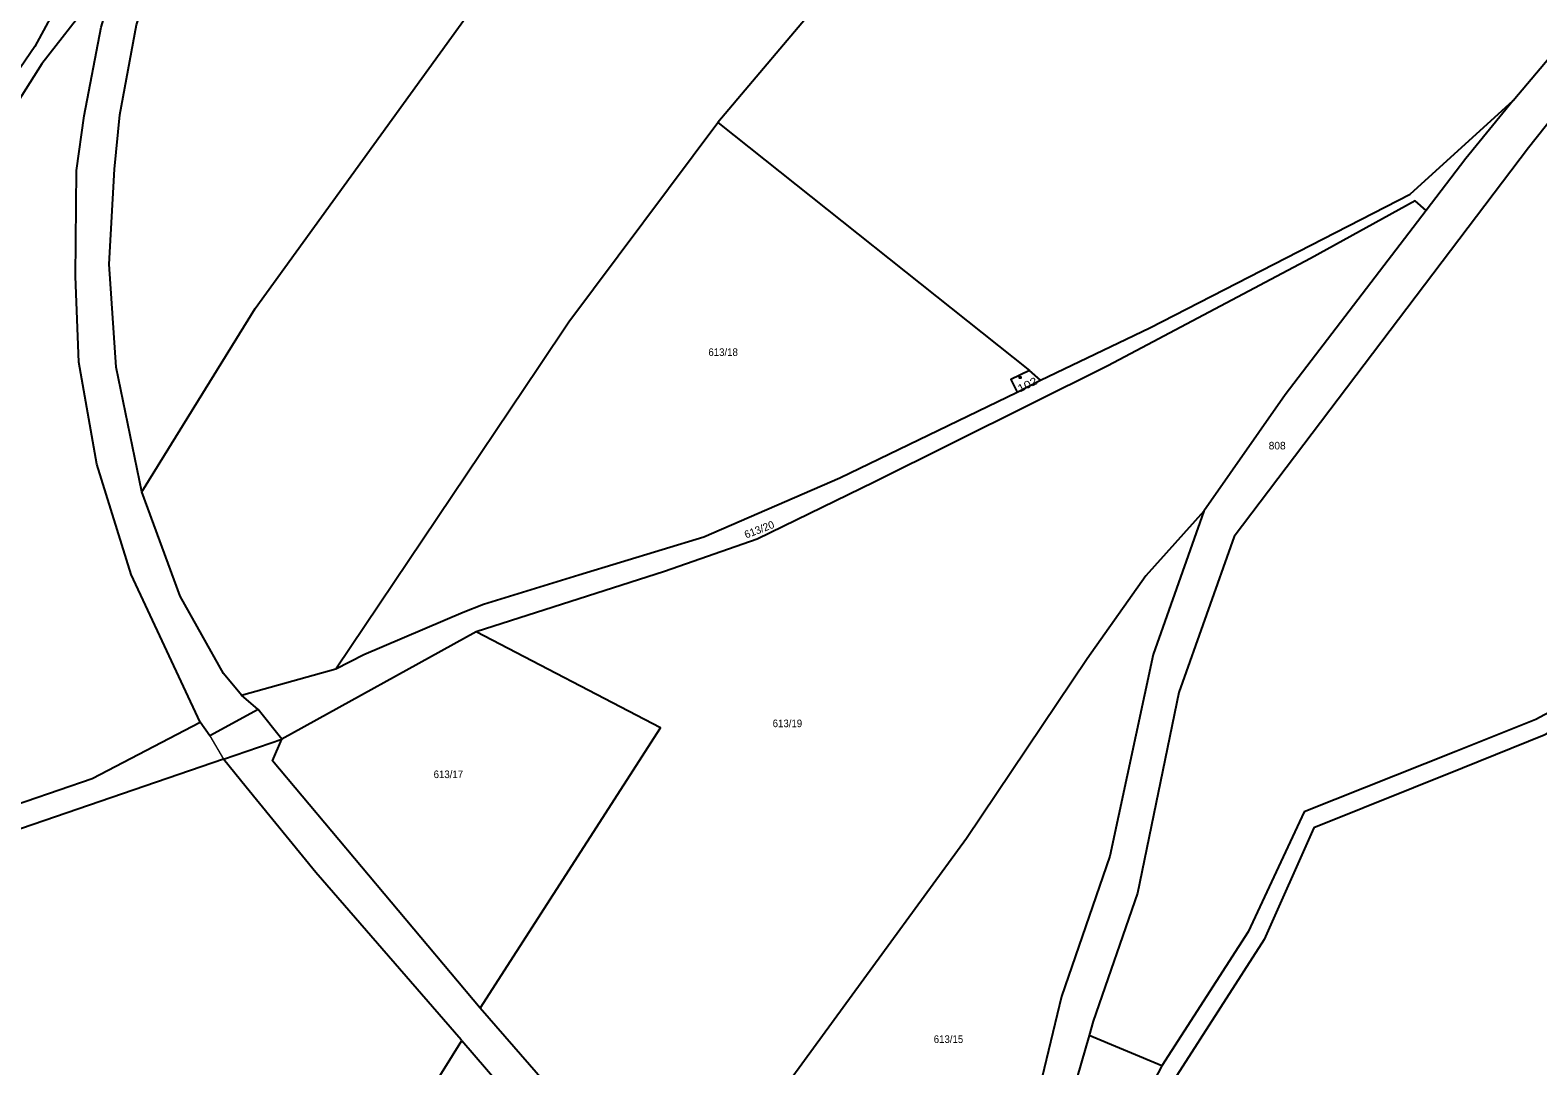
# Model space of a CAD drawing. Extents: x -687135 to -684370, y -1007309 to -1005782.
# Drawn here: x -684920.8 to -684583, y -1006550 to -1006317.9 of the extents above; entities that cross this region are included whole.
import ezdxf

# ---------------------------------------------------------------- set-up
doc = ezdxf.new("R2010")
doc.units = 0
doc.header["$LTSCALE"] = 0.68
for name, color, linetype, lineweight in [('1', 7, 'Continuous', 25), ('4', 7, 'Continuous', 13), ('5', 7, 'Continuous', 25)]:
    doc.layers.add(name, color=color, linetype=linetype, lineweight=lineweight)
doc.layers.add('2', color=7, linetype='Continuous')

msp = doc.modelspace()

# ---------------------------------------------------------------- linework, layer by layer
at = {"layer": '1'}
for p, q in [((-684820.88, -1006452.76), (-684864.38, -1006476.83)), ((-684873.47, -1006466.92), (-684852.35, -1006461.07)), ((-684869.72, -1006470.15), (-684873.47, -1006466.92)), ((-684667.28, -1006550.01), (-684683.56, -1006543.2))]:
    msp.add_line(p, q, dxfattribs=at)
for points in [[(-684895.75, -1006421.4), (-684901.52, -1006393.47), (-684903.13, -1006370.41), (-684901.9, -1006349.06), (-684900.72, -1006336.88), (-684896.95, -1006316.71), (-684891.31, -1006300.08), (-684874.68, -1006263.75), (-684861.12, -1006245.83), (-684849.13, -1006233.21), (-684838.04, -1006222.1), (-684820.16, -1006207.64), (-684803.79, -1006195.44), (-684787.9, -1006184.05), (-684728.55, -1006143.87), (-684695.61, -1006119.67)], [(-684895.75, -1006421.4), (-684870.4, -1006380.29), (-684822.32, -1006313.86), (-684813.73, -1006302.51), (-684789.44, -1006271.88), (-684758.27, -1006233.58), (-684701.91, -1006153.06), (-684685.37, -1006125.92), (-684682.73, -1006121.59)], [(-684594.2, -1006128.33), (-684596.65, -1006135.63), (-684614.36, -1006156.02), (-684631.3, -1006178.22), (-684688.55, -1006244.87), (-684727.25, -1006290.89), (-684742.63, -1006309.98), (-684766.71, -1006338.61), (-684696.92, -1006394.18)], [(-684465.61, -1006201.09), (-684474.26, -1006204.25), (-684488.16, -1006218.72), (-684538.26, -1006285.17), (-684585.17, -1006344.33), (-684651.09, -1006431.43), (-684663.47, -1006466.37), (-684672.76, -1006511.35), (-684682.63, -1006539.99), (-684683.56, -1006543.2)], [(-684856.23, -1006219.78), (-684868.36, -1006236.18), (-684877.16, -1006249.29), (-684887.91, -1006266.51), (-684898.63, -1006286.6), (-684913.88, -1006310.63), (-684919.75, -1006321.58), (-684931.87, -1006339.19), (-684939.11, -1006350.34), (-684952.01, -1006369.9), (-684965.12, -1006392.2), (-684970.59, -1006402.96), (-684973.76, -1006410.29), (-684980.32, -1006434.42)], [(-684588.56, -1006333.7), (-684566.02, -1006306.89), (-684551.05, -1006289.44)], [(-684900.57, -1006302.99), (-684907.23, -1006311.42), (-684918.18, -1006325.47), (-684932.07, -1006347.35), (-684944, -1006366.68), (-684955.53, -1006384.87), (-684969.03, -1006410.25), (-684975.28, -1006437.24), (-684977.83, -1006474.8), (-684979.92, -1006493.97)], [(-684882.68, -1006473.01), (-684898.16, -1006439.92), (-684905.85, -1006415.18), (-684909.93, -1006392.37), (-684910.65, -1006373.15), (-684910.41, -1006349.38), (-684908.73, -1006337.13), (-684904.89, -1006317.24), (-684900.57, -1006302.99)], [(-684394.08, -1006330.36), (-684455.26, -1006363.4), (-684477.77, -1006377.32), (-684500.17, -1006394.38), (-684524.62, -1006425.41), (-684535.71, -1006437.74), (-684546.54, -1006449.38), (-684559.48, -1006459.45), (-684583.52, -1006472.4), (-684601.39, -1006479.59), (-684635.43, -1006493.11), (-684647.97, -1006520), (-684667.28, -1006550.01)], [(-684392.01, -1006333.79), (-684453.16, -1006366.8), (-684475.35, -1006380.5), (-684497.75, -1006397.56), (-684521.48, -1006427.89), (-684532.78, -1006440.46), (-684543.61, -1006452.11), (-684557.02, -1006462.61), (-684581.63, -1006475.92), (-684599.9, -1006483.3), (-684633.2, -1006496.66), (-684644.34, -1006521.69), (-684663.91, -1006552.17), (-684694.22, -1006610.15), (-684711.78, -1006622.12)], [(-684694.47, -1006396.38), (-684669.99, -1006384.62), (-684611.65, -1006354.71), (-684588.56, -1006333.7)], [(-684588.56, -1006333.7), (-684599.19, -1006346.73), (-684608.09, -1006358.38)], [(-684852.35, -1006461.07), (-684806.76, -1006393.23), (-684800.1, -1006383.32), (-684766.71, -1006338.61)], [(-684608.09, -1006358.38), (-684610.52, -1006356.2), (-684633.97, -1006369.1), (-684679.41, -1006393.15), (-684731.7, -1006419.23), (-684757.91, -1006431.97), (-684778.7, -1006439.27), (-684820.88, -1006452.76)], [(-684608.09, -1006358.38), (-684639.65, -1006399.67), (-684657.89, -1006425.71)], [(-684696.92, -1006394.18), (-684701.1, -1006396.22), (-684699.72, -1006399.05)], [(-684699.72, -1006399.05), (-684694.47, -1006396.38), (-684696.92, -1006394.18)], [(-684852.35, -1006461.07), (-684846.05, -1006457.85), (-684823.77, -1006448.32), (-684819.22, -1006446.56), (-684797.87, -1006439.96), (-684769.87, -1006431.45), (-684739.38, -1006418.27), (-684699.72, -1006399.05)], [(-684873.47, -1006466.92), (-684877.5, -1006462.08), (-684887.16, -1006444.76), (-684895.75, -1006421.4)], [(-684657.89, -1006425.71), (-684670.89, -1006440.21), (-684684.04, -1006458.84), (-684711.02, -1006499.06), (-684729.99, -1006525.08), (-684751.95, -1006555.18), (-684776.01, -1006587.17)], [(-684657.89, -1006425.71), (-684669.24, -1006457.85), (-684678.91, -1006503.04), (-684689.78, -1006534.46), (-684695.59, -1006558.66), (-684701.01, -1006571.99), (-684705.84, -1006583.77), (-684707.61, -1006588.16)], [(-684819.96, -1006537.11), (-684779.58, -1006474.24), (-684820.88, -1006452.76)], [(-684869.72, -1006470.15), (-684880.58, -1006476.06), (-684882.68, -1006473.01)], [(-684877.48, -1006481.32), (-684864.38, -1006476.83), (-684869.72, -1006470.15)], [(-684979.92, -1006493.97), (-684948.43, -1006498.37), (-684929.18, -1006493.22), (-684906.88, -1006485.6), (-684882.68, -1006473.01)], [(-684819.96, -1006537.11), (-684866.49, -1006481.68), (-684864.38, -1006476.83)], [(-684877.48, -1006481.32), (-684932.8, -1006500.28), (-684949.95, -1006504.09), (-684980.95, -1006503.36), (-685010.09, -1006519.79)], [(-684824.1, -1006544.38), (-684824.23, -1006544.23), (-684856.83, -1006506.68), (-684872.39, -1006487.57), (-684877.48, -1006481.32)], [(-685010.09, -1006519.79), (-684993.05, -1006534.8), (-684954.59, -1006567.81), (-684941.96, -1006578.76), (-684935.76, -1006584.14), (-684920.1, -1006597.74), (-684868.88, -1006616.37), (-684824.1, -1006544.38)], [(-684776.01, -1006587.17), (-684785.34, -1006576.89), (-684819.96, -1006537.11)], [(-684824.1, -1006544.38), (-684781.26, -1006594.14), (-684749.97, -1006631.36)], [(-684683.56, -1006543.2), (-684689.74, -1006564.65), (-684710.44, -1006616.37)], [(-684667.28, -1006550.01), (-684697.76, -1006608.3), (-684710.44, -1006616.37), (-684711.78, -1006622.12)]]:
    msp.add_lwpolyline(points, dxfattribs=at)
at = {"layer": '4'}
msp.add_line((-684880.58, -1006476.06), (-684877.48, -1006481.32), dxfattribs=at)
at = {"layer": '5'}
msp.add_circle((-684699.0168, -1006395.7792), 0.175, dxfattribs=at)

# ---------------------------------------------------------------- texts
at = {"layer": '2', "width": 0.95}
for s, p in [('613/18', (-684768.86, -1006390.94)), ('613/19', (-684754.46, -1006474.13)), ('613/17', (-684830.41, -1006485.539)), ('613/15', (-684718.38, -1006544.89))]:
    msp.add_text(s, height=1.7, dxfattribs=at).set_placement(p)
at = {"layer": '2', "width": 1.2}
msp.add_text('102', height=1.7, rotation=26, dxfattribs=at).set_placement((-684699.067, -1006399.133))
at = {"layer": '2'}
msp.add_text('808', height=1.7, dxfattribs=at).set_placement((-684643.34, -1006411.89))
msp.add_text('613/20', height=1.7, rotation=21, dxfattribs=at).set_placement((-684760.405, -1006431.873))

doc.saveas('drawing.dxf')
